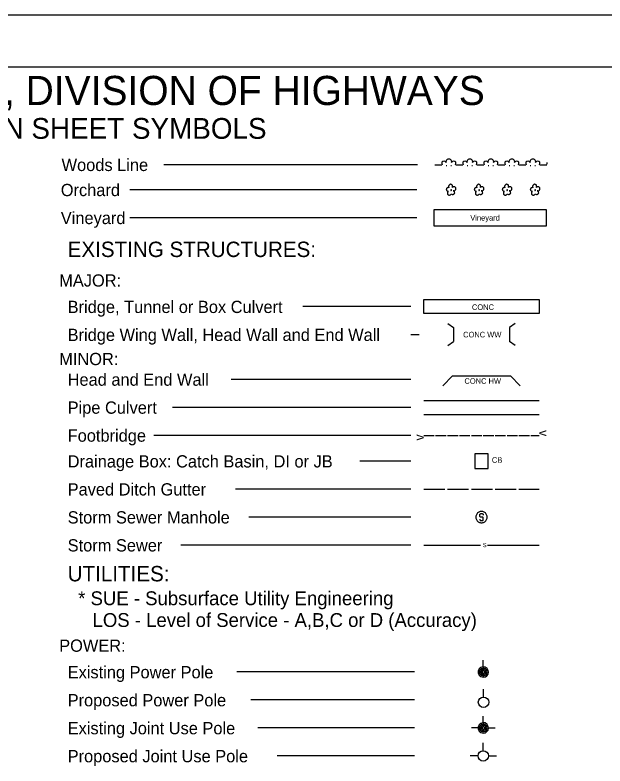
# Model space of a CAD drawing. Extents: x 1552903 to 1553044, y 811448 to 811540.
# Drawn here: x 1552973.4 to 1553008.81, y 811494.96 to 811540.09 of the extents above; entities that cross this region are included whole.
import ezdxf

# ---------------------------------------------------------------- set-up
doc = ezdxf.new("R2010")
doc.units = 0
for name, color, linetype in [('Exist DTM Breakline', 7, 'Continuous'), ('Exist Structure Major Bridge WW', 7, 'Continuous'), ('z - Construction', 7, 'Continuous')]:
    doc.layers.add(name, color=color, linetype=linetype)

msp = doc.modelspace()

# ---------------------------------------------------------------- linework, layer by layer
at = {"layer": 'Exist DTM Breakline'}
for p, q in [((1552997.561, 811531.092), (1552982.332, 811531.092)), ((1552998.603, 811531.092), (1552999.023, 811531.092)), ((1552999.271, 811531.05), (1552999.313, 811531.05)), ((1552999.566, 811531.05), (1552999.608, 811531.05)), ((1552999.864, 811531.092), (1553000.285, 811531.092)), ((1553000.533, 811531.05), (1553000.575, 811531.05)), ((1553000.827, 811531.05), (1553000.869, 811531.05)), ((1553001.125, 811531.092), (1553001.546, 811531.092)), ((1553001.794, 811531.05), (1553001.836, 811531.05)), ((1553002.088, 811531.05), (1553002.13, 811531.05)), ((1553002.386, 811531.092), (1553002.807, 811531.092)), ((1553003.055, 811531.05), (1553003.097, 811531.05)), ((1553003.349, 811531.05), (1553003.391, 811531.05)), ((1553003.648, 811531.092), (1553004.068, 811531.092)), ((1553004.316, 811531.05), (1553004.358, 811531.05)), ((1553004.61, 811531.05), (1553004.652, 811531.05)), ((1553004.909, 811531.092), (1553005.329, 811531.092)), ((1552997.514, 811529.585), (1552980.283, 811529.585)), ((1552997.514, 811527.903), (1552980.283, 811527.903)), ((1552997.151, 811522.564), (1552990.679, 811522.564)), ((1552999.375, 811521.543), (1552999.719, 811521.303)), ((1552999.719, 811521.303), (1552999.719, 811520.462)), ((1553003.427, 811521.543), (1553003.082, 811521.303)), ((1553003.082, 811521.303), (1553003.082, 811520.462)), ((1552997.151, 811520.882), (1552997.654, 811520.882)), ((1552999.375, 811520.221), (1552999.719, 811520.462)), ((1553003.427, 811520.221), (1553003.082, 811520.462)), ((1552997.151, 811518.192), (1552986.363, 811518.192)), ((1552999.072, 811517.808), (1552999.667, 811518.403)), ((1552999.667, 811518.403), (1553003.135, 811518.403)), ((1553003.135, 811518.403), (1553003.73, 811517.808)), ((1552997.933, 811516.931), (1553004.869, 811516.931)), ((1552997.151, 811516.511), (1552982.842, 811516.511)), ((1552997.933, 811516.09), (1553004.869, 811516.09)), ((1552997.151, 811514.829), (1552981.724, 811514.829)), ((1552997.933, 811514.829), (1552998.563, 811514.829)), ((1552998.647, 811514.829), (1552999.278, 811514.829)), ((1552999.362, 811514.829), (1552999.993, 811514.829)), ((1553000.077, 811514.829), (1553000.707, 811514.829)), ((1553000.791, 811514.829), (1553001.422, 811514.829)), ((1553001.506, 811514.829), (1553002.137, 811514.829)), ((1553002.221, 811514.829), (1553002.851, 811514.829)), ((1553002.935, 811514.829), (1553003.566, 811514.829)), ((1553003.65, 811514.829), (1553004.28, 811514.829)), ((1553004.365, 811514.829), (1553004.869, 811514.829)), ((1552997.151, 811513.279), (1552994.099, 811513.279)), ((1552997.151, 811511.598), (1552986.625, 811511.598)), ((1552997.933, 811511.598), (1552999.194, 811511.598)), ((1552999.362, 811511.598), (1553000.623, 811511.598)), ((1553000.791, 811511.598), (1553002.052, 811511.598)), ((1553002.221, 811511.598), (1553003.482, 811511.598)), ((1553003.65, 811511.598), (1553004.869, 811511.598)), ((1552997.151, 811509.916), (1552987.425, 811509.916)), ((1553001.3, 811509.976), (1553001.3, 811510.066)), ((1553001.36, 811510.126), (1553001.45, 811510.126)), ((1553001.45, 811509.919), (1553001.36, 811509.919)), ((1553001.507, 811510.066), (1553001.507, 811510.036)), ((1553001.3, 811509.798), (1553001.3, 811509.768)), ((1553001.36, 811509.711), (1553001.45, 811509.711)), ((1553001.507, 811509.768), (1553001.507, 811509.861)), ((1552997.151, 811508.234), (1552983.345, 811508.234)), ((1552997.933, 811508.234), (1553001.34, 811508.234)), ((1553001.76, 811508.234), (1553004.869, 811508.234)), ((1553001.506, 811500.92), (1553001.506, 811501.324)), ((1552997.385, 811500.61), (1552986.718, 811500.61)), ((1553001.524, 811499.106), (1553001.524, 811499.579)), ((1552997.385, 811498.928), (1552987.549, 811498.928)), ((1553001.506, 811497.557), (1553001.506, 811497.961)), ((1552997.385, 811497.247), (1552987.976, 811497.247)), ((1553001.196, 811497.247), (1553000.792, 811497.247)), ((1553001.816, 811497.247), (1553002.22, 811497.247)), ((1553001.506, 811495.882), (1553001.506, 811496.355)), ((1552997.385, 811495.565), (1552989.126, 811495.565)), ((1553001.191, 811495.566), (1553000.718, 811495.566)), ((1553001.821, 811495.566), (1553002.294, 811495.566))]:
    msp.add_line(p, q, dxfattribs=at)
for points in [[(1552999.653, 811529.732), (1552999.665, 811529.757), (1552999.669, 811529.783), (1552999.665, 811529.808), (1552999.661, 811529.833), (1552999.648, 811529.854), (1552999.636, 811529.875), (1552999.615, 811529.892), (1552999.594, 811529.904), (1552999.564, 811529.913), (1552999.543, 811529.913), (1552999.518, 811529.909), (1552999.493, 811529.9), (1552999.472, 811529.888), (1552999.451, 811529.871), (1552999.438, 811529.846), (1552999.43, 811529.825), (1552999.426, 811529.799), (1552999.426, 811529.774), (1552999.43, 811529.749), (1552999.442, 811529.728), (1552999.459, 811529.703), (1552999.438, 811529.715), (1552999.413, 811529.719), (1552999.388, 811529.719), (1552999.367, 811529.711), (1552999.346, 811529.703), (1552999.325, 811529.686), (1552999.308, 811529.669), (1552999.295, 811529.648), (1552999.291, 811529.627), (1552999.287, 811529.598), (1552999.291, 811529.577), (1552999.3, 811529.556), (1552999.316, 811529.534), (1552999.329, 811529.518), (1552999.35, 811529.505), (1552999.375, 811529.492), (1552999.396, 811529.488), (1552999.421, 811529.488), (1552999.4, 811529.48), (1552999.379, 811529.463), (1552999.367, 811529.446), (1552999.358, 811529.421), (1552999.35, 811529.396), (1552999.35, 811529.375), (1552999.354, 811529.35), (1552999.367, 811529.329), (1552999.379, 811529.307), (1552999.396, 811529.291), (1552999.417, 811529.278), (1552999.438, 811529.27), (1552999.463, 811529.27), (1552999.489, 811529.27), (1552999.51, 811529.274), (1552999.531, 811529.291), (1552999.552, 811529.303), (1552999.573, 811529.341)], [(1552999.573, 811529.341), (1552999.623, 811529.312), (1552999.648, 811529.303), (1552999.674, 811529.299), (1552999.699, 811529.303), (1552999.72, 811529.312), (1552999.741, 811529.324), (1552999.762, 811529.341), (1552999.775, 811529.362), (1552999.783, 811529.383), (1552999.791, 811529.408), (1552999.787, 811529.434), (1552999.783, 811529.459), (1552999.766, 811529.484), (1552999.754, 811529.501), (1552999.733, 811529.513), (1552999.707, 811529.526), (1552999.733, 811529.522), (1552999.762, 811529.522), (1552999.783, 811529.53), (1552999.808, 811529.543), (1552999.829, 811529.556), (1552999.846, 811529.577), (1552999.859, 811529.602), (1552999.863, 811529.627), (1552999.867, 811529.652), (1552999.863, 811529.677), (1552999.854, 811529.703), (1552999.838, 811529.724), (1552999.817, 811529.745), (1552999.796, 811529.757), (1552999.77, 811529.766), (1552999.745, 811529.77), (1552999.72, 811529.77), (1552999.695, 811529.762), (1552999.674, 811529.749), (1552999.653, 811529.732)], [(1553001.334, 811529.732), (1553001.347, 811529.757), (1553001.351, 811529.783), (1553001.347, 811529.808), (1553001.343, 811529.833), (1553001.33, 811529.854), (1553001.317, 811529.875), (1553001.296, 811529.892), (1553001.275, 811529.904), (1553001.246, 811529.913), (1553001.225, 811529.913), (1553001.2, 811529.909), (1553001.174, 811529.9), (1553001.153, 811529.888), (1553001.132, 811529.871), (1553001.12, 811529.846), (1553001.111, 811529.825), (1553001.107, 811529.799), (1553001.107, 811529.774), (1553001.111, 811529.749), (1553001.124, 811529.728), (1553001.141, 811529.703), (1553001.12, 811529.715), (1553001.095, 811529.719), (1553001.069, 811529.719), (1553001.048, 811529.711), (1553001.027, 811529.703), (1553001.006, 811529.686), (1553000.99, 811529.669), (1553000.977, 811529.648), (1553000.973, 811529.627), (1553000.968, 811529.598), (1553000.973, 811529.577), (1553000.981, 811529.556), (1553000.998, 811529.534), (1553001.011, 811529.518), (1553001.032, 811529.505), (1553001.057, 811529.492), (1553001.078, 811529.488), (1553001.103, 811529.488), (1553001.082, 811529.48), (1553001.061, 811529.463), (1553001.048, 811529.446), (1553001.04, 811529.421), (1553001.032, 811529.396), (1553001.032, 811529.375), (1553001.036, 811529.35), (1553001.048, 811529.329), (1553001.061, 811529.307), (1553001.078, 811529.291), (1553001.099, 811529.278), (1553001.12, 811529.27), (1553001.145, 811529.27), (1553001.17, 811529.27), (1553001.191, 811529.274), (1553001.212, 811529.291), (1553001.233, 811529.303), (1553001.254, 811529.341)], [(1553001.254, 811529.341), (1553001.305, 811529.312), (1553001.33, 811529.303), (1553001.355, 811529.299), (1553001.38, 811529.303), (1553001.401, 811529.312), (1553001.423, 811529.324), (1553001.444, 811529.341), (1553001.456, 811529.362), (1553001.465, 811529.383), (1553001.473, 811529.408), (1553001.469, 811529.434), (1553001.465, 811529.459), (1553001.448, 811529.484), (1553001.435, 811529.501), (1553001.414, 811529.513), (1553001.389, 811529.526), (1553001.414, 811529.522), (1553001.444, 811529.522), (1553001.465, 811529.53), (1553001.49, 811529.543), (1553001.511, 811529.556), (1553001.528, 811529.577), (1553001.54, 811529.602), (1553001.544, 811529.627), (1553001.549, 811529.652), (1553001.544, 811529.677), (1553001.536, 811529.703), (1553001.519, 811529.724), (1553001.498, 811529.745), (1553001.477, 811529.757), (1553001.452, 811529.766), (1553001.427, 811529.77), (1553001.401, 811529.77), (1553001.376, 811529.762), (1553001.355, 811529.749), (1553001.334, 811529.732)], [(1553003.016, 811529.732), (1553003.028, 811529.757), (1553003.033, 811529.783), (1553003.028, 811529.808), (1553003.024, 811529.833), (1553003.012, 811529.854), (1553002.999, 811529.875), (1553002.978, 811529.892), (1553002.957, 811529.904), (1553002.928, 811529.913), (1553002.906, 811529.913), (1553002.881, 811529.909), (1553002.856, 811529.9), (1553002.835, 811529.888), (1553002.814, 811529.871), (1553002.801, 811529.846), (1553002.793, 811529.825), (1553002.789, 811529.799), (1553002.789, 811529.774), (1553002.793, 811529.749), (1553002.806, 811529.728), (1553002.822, 811529.703), (1553002.801, 811529.715), (1553002.776, 811529.719), (1553002.751, 811529.719), (1553002.73, 811529.711), (1553002.709, 811529.703), (1553002.688, 811529.686), (1553002.671, 811529.669), (1553002.658, 811529.648), (1553002.654, 811529.627), (1553002.65, 811529.598), (1553002.654, 811529.577), (1553002.663, 811529.556), (1553002.679, 811529.534), (1553002.692, 811529.518), (1553002.713, 811529.505), (1553002.738, 811529.492), (1553002.759, 811529.488), (1553002.785, 811529.488), (1553002.764, 811529.48), (1553002.743, 811529.463), (1553002.73, 811529.446), (1553002.722, 811529.421), (1553002.713, 811529.396), (1553002.713, 811529.375), (1553002.717, 811529.35), (1553002.73, 811529.329), (1553002.743, 811529.307), (1553002.759, 811529.291), (1553002.78, 811529.278), (1553002.801, 811529.27), (1553002.827, 811529.27), (1553002.852, 811529.27), (1553002.873, 811529.274), (1553002.894, 811529.291), (1553002.915, 811529.303), (1553002.936, 811529.341)], [(1553002.936, 811529.341), (1553002.986, 811529.312), (1553003.012, 811529.303), (1553003.037, 811529.299), (1553003.062, 811529.303), (1553003.083, 811529.312), (1553003.104, 811529.324), (1553003.125, 811529.341), (1553003.138, 811529.362), (1553003.146, 811529.383), (1553003.155, 811529.408), (1553003.15, 811529.434), (1553003.146, 811529.459), (1553003.129, 811529.484), (1553003.117, 811529.501), (1553003.096, 811529.513), (1553003.07, 811529.526), (1553003.096, 811529.522), (1553003.125, 811529.522), (1553003.146, 811529.53), (1553003.171, 811529.543), (1553003.192, 811529.556), (1553003.209, 811529.577), (1553003.222, 811529.602), (1553003.226, 811529.627), (1553003.23, 811529.652), (1553003.226, 811529.677), (1553003.218, 811529.703), (1553003.201, 811529.724), (1553003.18, 811529.745), (1553003.159, 811529.757), (1553003.134, 811529.766), (1553003.108, 811529.77), (1553003.083, 811529.77), (1553003.058, 811529.762), (1553003.037, 811529.749), (1553003.016, 811529.732)], [(1553004.697, 811529.732), (1553004.71, 811529.757), (1553004.714, 811529.783), (1553004.71, 811529.808), (1553004.706, 811529.833), (1553004.693, 811529.854), (1553004.681, 811529.875), (1553004.66, 811529.892), (1553004.639, 811529.904), (1553004.609, 811529.913), (1553004.588, 811529.913), (1553004.563, 811529.909), (1553004.538, 811529.9), (1553004.517, 811529.888), (1553004.496, 811529.871), (1553004.483, 811529.846), (1553004.475, 811529.825), (1553004.47, 811529.799), (1553004.47, 811529.774), (1553004.475, 811529.749), (1553004.487, 811529.728), (1553004.504, 811529.703), (1553004.483, 811529.715), (1553004.458, 811529.719), (1553004.433, 811529.719), (1553004.411, 811529.711), (1553004.39, 811529.703), (1553004.369, 811529.686), (1553004.353, 811529.669), (1553004.34, 811529.648), (1553004.336, 811529.627), (1553004.332, 811529.598), (1553004.336, 811529.577), (1553004.344, 811529.556), (1553004.361, 811529.534), (1553004.374, 811529.518), (1553004.395, 811529.505), (1553004.42, 811529.492), (1553004.441, 811529.488), (1553004.466, 811529.488), (1553004.445, 811529.48), (1553004.424, 811529.463), (1553004.411, 811529.446), (1553004.403, 811529.421), (1553004.395, 811529.396), (1553004.395, 811529.375), (1553004.399, 811529.35), (1553004.411, 811529.329), (1553004.424, 811529.307), (1553004.441, 811529.291), (1553004.462, 811529.278), (1553004.483, 811529.27), (1553004.508, 811529.27), (1553004.533, 811529.27), (1553004.554, 811529.274), (1553004.575, 811529.291), (1553004.596, 811529.303), (1553004.617, 811529.341)], [(1553004.617, 811529.341), (1553004.668, 811529.312), (1553004.693, 811529.303), (1553004.718, 811529.299), (1553004.744, 811529.303), (1553004.765, 811529.312), (1553004.786, 811529.324), (1553004.807, 811529.341), (1553004.819, 811529.362), (1553004.828, 811529.383), (1553004.836, 811529.408), (1553004.832, 811529.434), (1553004.828, 811529.459), (1553004.811, 811529.484), (1553004.798, 811529.501), (1553004.777, 811529.513), (1553004.752, 811529.526), (1553004.777, 811529.522), (1553004.807, 811529.522), (1553004.828, 811529.53), (1553004.853, 811529.543), (1553004.874, 811529.556), (1553004.891, 811529.577), (1553004.903, 811529.602), (1553004.908, 811529.627), (1553004.912, 811529.652), (1553004.908, 811529.677), (1553004.899, 811529.703), (1553004.882, 811529.724), (1553004.861, 811529.745), (1553004.84, 811529.757), (1553004.815, 811529.766), (1553004.79, 811529.77), (1553004.765, 811529.77), (1553004.739, 811529.762), (1553004.718, 811529.749), (1553004.697, 811529.732)], [(1552999.581, 811529.585), (1552999.569, 811529.585), (1552999.56, 811529.581), (1552999.552, 811529.577), (1552999.552, 811529.564), (1552999.552, 811529.556), (1552999.56, 811529.547), (1552999.573, 811529.547), (1552999.581, 811529.547), (1552999.59, 811529.556), (1552999.594, 811529.568), (1552999.59, 811529.577), (1552999.581, 811529.585)], [(1553001.263, 811529.585), (1553001.25, 811529.585), (1553001.242, 811529.581), (1553001.233, 811529.577), (1553001.233, 811529.564), (1553001.233, 811529.556), (1553001.242, 811529.547), (1553001.254, 811529.547), (1553001.263, 811529.547), (1553001.271, 811529.556), (1553001.275, 811529.568), (1553001.271, 811529.577), (1553001.263, 811529.585)], [(1553002.944, 811529.585), (1553002.932, 811529.585), (1553002.923, 811529.581), (1553002.915, 811529.577), (1553002.915, 811529.564), (1553002.915, 811529.556), (1553002.923, 811529.547), (1553002.936, 811529.547), (1553002.944, 811529.547), (1553002.953, 811529.556), (1553002.957, 811529.568), (1553002.953, 811529.577), (1553002.944, 811529.585)], [(1553004.626, 811529.585), (1553004.613, 811529.585), (1553004.605, 811529.581), (1553004.596, 811529.577), (1553004.596, 811529.564), (1553004.596, 811529.556), (1553004.605, 811529.547), (1553004.617, 811529.547), (1553004.626, 811529.547), (1553004.634, 811529.556), (1553004.639, 811529.568), (1553004.634, 811529.577), (1553004.626, 811529.585)], [(1552998.555, 811528.408), (1553005.282, 811528.408), (1553005.282, 811527.399), (1552998.555, 811527.399), (1552998.555, 811528.408)], [(1552997.933, 811522.984), (1553004.869, 811522.984), (1553004.869, 811522.144), (1552997.933, 811522.144), (1552997.933, 811522.984)], [(1553001.401, 811510.257), (1553001.357, 811510.255), (1553001.316, 811510.246), (1553001.275, 811510.233), (1553001.237, 811510.214), (1553001.201, 811510.192), (1553001.169, 811510.164), (1553001.139, 811510.132), (1553001.114, 811510.099), (1553001.092, 811510.061), (1553001.079, 811510.02), (1553001.068, 811509.979), (1553001.062, 811509.938), (1553001.062, 811509.894), (1553001.068, 811509.853), (1553001.079, 811509.81), (1553001.092, 811509.771), (1553001.114, 811509.733), (1553001.139, 811509.7), (1553001.169, 811509.667), (1553001.201, 811509.64), (1553001.237, 811509.618), (1553001.275, 811509.599), (1553001.316, 811509.585), (1553001.36, 811509.577), (1553001.401, 811509.575), (1553001.445, 811509.577), (1553001.485, 811509.585), (1553001.526, 811509.599), (1553001.565, 811509.618), (1553001.6, 811509.64), (1553001.633, 811509.667), (1553001.663, 811509.7), (1553001.688, 811509.733), (1553001.709, 811509.771), (1553001.723, 811509.812), (1553001.734, 811509.853), (1553001.739, 811509.894), (1553001.739, 811509.938), (1553001.734, 811509.979), (1553001.723, 811510.022), (1553001.709, 811510.061), (1553001.688, 811510.099), (1553001.663, 811510.132), (1553001.633, 811510.164), (1553001.6, 811510.192), (1553001.565, 811510.214), (1553001.526, 811510.233), (1553001.485, 811510.246), (1553001.442, 811510.255), (1553001.401, 811510.257)], [(1553001.3, 811510.066), (1553001.305, 811510.085), (1553001.313, 811510.102), (1553001.324, 811510.113), (1553001.341, 811510.121), (1553001.36, 811510.126)], [(1553001.36, 811509.919), (1553001.341, 811509.921), (1553001.324, 811509.93), (1553001.313, 811509.943), (1553001.305, 811509.96), (1553001.3, 811509.976)], [(1553001.45, 811510.126), (1553001.466, 811510.121), (1553001.483, 811510.113), (1553001.496, 811510.102), (1553001.505, 811510.085), (1553001.507, 811510.066)], [(1553001.507, 811509.859), (1553001.505, 811509.878), (1553001.496, 811509.894), (1553001.483, 811509.908), (1553001.466, 811509.916), (1553001.45, 811509.919)], [(1553001.3, 811509.771), (1553001.305, 811509.752), (1553001.313, 811509.736), (1553001.324, 811509.722), (1553001.341, 811509.714), (1553001.36, 811509.711)], [(1553001.45, 811509.711), (1553001.466, 811509.714), (1553001.483, 811509.722), (1553001.496, 811509.736), (1553001.505, 811509.752), (1553001.507, 811509.771)], [(1553001.736, 811500.61), (1553001.729, 811500.666), (1553001.711, 811500.716), (1553001.68, 811500.759), (1553001.642, 811500.796), (1553001.599, 811500.821), (1553001.543, 811500.833), (1553001.493, 811500.84), (1553001.438, 811500.827), (1553001.388, 811500.809), (1553001.351, 811500.778), (1553001.314, 811500.734), (1553001.289, 811500.691), (1553001.276, 811500.635), (1553001.276, 811500.585), (1553001.289, 811500.529), (1553001.314, 811500.486), (1553001.351, 811500.442), (1553001.388, 811500.411), (1553001.438, 811500.393), (1553001.493, 811500.38), (1553001.543, 811500.387), (1553001.599, 811500.399), (1553001.642, 811500.424), (1553001.68, 811500.461), (1553001.711, 811500.505), (1553001.729, 811500.554), (1553001.736, 811500.61)], [(1553001.661, 811500.61), (1553001.655, 811500.654), (1553001.636, 811500.697), (1553001.605, 811500.728), (1553001.568, 811500.753), (1553001.531, 811500.765), (1553001.481, 811500.765), (1553001.444, 811500.753), (1553001.407, 811500.728), (1553001.376, 811500.697), (1553001.357, 811500.654), (1553001.351, 811500.61), (1553001.357, 811500.567), (1553001.376, 811500.523), (1553001.407, 811500.492), (1553001.444, 811500.467), (1553001.481, 811500.455), (1553001.531, 811500.455), (1553001.568, 811500.467), (1553001.605, 811500.492), (1553001.636, 811500.523), (1553001.655, 811500.567), (1553001.661, 811500.61)], [(1553001.58, 811500.61), (1553001.574, 811500.641), (1553001.556, 811500.666), (1553001.531, 811500.678), (1553001.5, 811500.685), (1553001.469, 811500.672), (1553001.444, 811500.654), (1553001.431, 811500.623), (1553001.431, 811500.598), (1553001.444, 811500.567), (1553001.469, 811500.548), (1553001.5, 811500.536), (1553001.531, 811500.542), (1553001.556, 811500.554), (1553001.574, 811500.579), (1553001.58, 811500.61)], [(1553001.736, 811497.247), (1553001.729, 811497.303), (1553001.711, 811497.352), (1553001.68, 811497.396), (1553001.642, 811497.433), (1553001.599, 811497.458), (1553001.543, 811497.47), (1553001.493, 811497.477), (1553001.438, 811497.464), (1553001.388, 811497.446), (1553001.351, 811497.415), (1553001.314, 811497.371), (1553001.289, 811497.328), (1553001.276, 811497.272), (1553001.276, 811497.222), (1553001.289, 811497.166), (1553001.314, 811497.123), (1553001.351, 811497.079), (1553001.388, 811497.048), (1553001.438, 811497.03), (1553001.493, 811497.017), (1553001.543, 811497.024), (1553001.599, 811497.036), (1553001.642, 811497.061), (1553001.68, 811497.098), (1553001.711, 811497.141), (1553001.729, 811497.191), (1553001.736, 811497.247)], [(1553001.661, 811497.247), (1553001.655, 811497.29), (1553001.636, 811497.334), (1553001.605, 811497.365), (1553001.568, 811497.39), (1553001.531, 811497.402), (1553001.481, 811497.402), (1553001.444, 811497.39), (1553001.407, 811497.365), (1553001.376, 811497.334), (1553001.357, 811497.29), (1553001.351, 811497.247), (1553001.357, 811497.203), (1553001.376, 811497.16), (1553001.407, 811497.129), (1553001.444, 811497.104), (1553001.481, 811497.092), (1553001.531, 811497.092), (1553001.568, 811497.104), (1553001.605, 811497.129), (1553001.636, 811497.16), (1553001.655, 811497.203), (1553001.661, 811497.247)], [(1553001.58, 811497.247), (1553001.574, 811497.278), (1553001.556, 811497.303), (1553001.531, 811497.315), (1553001.5, 811497.321), (1553001.469, 811497.309), (1553001.444, 811497.29), (1553001.431, 811497.259), (1553001.431, 811497.234), (1553001.444, 811497.203), (1553001.469, 811497.185), (1553001.5, 811497.172), (1553001.531, 811497.179), (1553001.556, 811497.191), (1553001.574, 811497.216), (1553001.58, 811497.247)]]:
    msp.add_lwpolyline(points, dxfattribs=at)
for points in [[(1553000.996, 811512.832), (1553001.804, 811512.832), (1553001.804, 811513.727), (1553000.996, 811513.727)], [(1553001.506, 811500.3), (1553001.636, 811500.324), (1553001.723, 811500.387), (1553001.791, 811500.474), (1553001.816, 811500.591), (1553001.804, 811500.703), (1553001.742, 811500.815), (1553001.618, 811500.908), (1553001.475, 811500.92), (1553001.351, 811500.883), (1553001.252, 811500.796), (1553001.202, 811500.678), (1553001.202, 811500.542), (1553001.252, 811500.424), (1553001.363, 811500.331)], [(1553001.506, 811496.937), (1553001.636, 811496.961), (1553001.723, 811497.024), (1553001.791, 811497.11), (1553001.816, 811497.228), (1553001.804, 811497.34), (1553001.742, 811497.452), (1553001.618, 811497.545), (1553001.475, 811497.557), (1553001.351, 811497.52), (1553001.252, 811497.433), (1553001.202, 811497.315), (1553001.202, 811497.179), (1553001.252, 811497.061), (1553001.363, 811496.968)]]:
    msp.add_lwpolyline(points, close=True, dxfattribs=at)
for centre in [(1553001.524, 811498.791), (1553001.506, 811495.565)]:
    msp.add_circle(centre, 0.315, dxfattribs=at)
for centre, radius, start, end in [((1552999.145, 811531.178), 0.133, 18.435, 219.2315), ((1552999.44, 811531.262), 0.173, 345.9638, 194.0362), ((1552999.734, 811531.178), 0.133, 320.7685, 161.5651), ((1553000.406, 811531.178), 0.133, 18.435, 219.2315), ((1553000.701, 811531.262), 0.173, 345.9638, 194.0362), ((1553000.995, 811531.178), 0.133, 320.7685, 161.5651), ((1553001.667, 811531.178), 0.133, 18.435, 219.2315), ((1553001.962, 811531.262), 0.173, 345.9638, 194.0362), ((1553002.256, 811531.178), 0.133, 320.7685, 161.5651), ((1553002.929, 811531.178), 0.133, 18.435, 219.2315), ((1553003.223, 811531.262), 0.173, 345.9638, 194.0362), ((1553003.517, 811531.178), 0.133, 320.7685, 161.5651), ((1553004.19, 811531.178), 0.133, 18.435, 219.2315), ((1553004.484, 811531.262), 0.173, 345.9638, 194.0362), ((1553004.778, 811531.178), 0.133, 320.7685, 161.5651), ((1553005.451, 811531.178), 0.133, 156.251, 203.749)]:
    msp.add_arc(centre, radius, start, end, dxfattribs=at)
at = {"layer": 'Exist Structure Major Bridge WW'}
msp.add_line((1553041.105, 811536.962), (1552905.688, 811536.962), dxfattribs=at)
at = {"layer": 'z - Construction'}
msp.add_line((1553044.23, 811540.087), (1552902.563, 811540.087), dxfattribs=at)

# ---------------------------------------------------------------- texts
at = {"layer": 'Exist DTM Breakline'}
for s, height, p in [('STATE OF NORTH CAROLINA, DIVISION OF HIGHWAYS', 1.75, (1552939.708, 811534.68)), ('CONVENTIONAL  PLAN SHEET SYMBOLS', 1.25, (1552955.429, 811532.649)), ('Woods Line', 0.7357, (1552976.192, 811530.712)), ('Orchard', 0.7357, (1552976.144, 811529.204)), ('Vineyard', 0.7357, (1552976.144, 811527.523)), ('EXISTING STRUCTURES:', 0.92486, (1552976.555, 811525.544)), ('MAJOR:', 0.7357, (1552976.048, 811523.769)), ('Bridge, Tunnel or Box Culvert', 0.73569, (1552976.555, 811522.181)), ('CONC', 0.3363, (1553000.828, 811522.365)), ('Bridge Wing Wall, Head Wall and End Wall', 0.73569, (1552976.555, 811520.5)), ('MINOR:', 0.7357, (1552976.048, 811519.05)), ('Head and End Wall', 0.73569, (1552976.555, 811517.81)), ('CONC HW', 0.3363, (1553000.375, 811517.926)), ('Pipe Culvert', 0.73569, (1552976.555, 811516.129)), ('Footbridge', 0.7357, (1552976.556, 811514.448)), ('Drainage Box: Catch Basin, DI or JB', 0.73569, (1552976.556, 811512.898)), ('CB', 0.3363, (1553002.026, 811513.18)), ('Paved Ditch Gutter', 0.73569, (1552976.556, 811511.215)), ('Storm Sewer Manhole', 0.73569, (1552976.556, 811509.533)), ('Storm Sewer', 0.73569, (1552976.556, 811507.852)), ('S', 0.252, (1553001.474, 811508.108)), ('UTILITIES:', 0.9249, (1552976.555, 811506.055)), ('* SUE - Subsurface Utility Engineering', 0.83238, (1552977.188, 811504.624)), ('LOS - Level of Service - A,B,C or D (Accuracy) ', 0.83238, (1552978.051, 811503.315)), ('POWER:', 0.7357, (1552976.048, 811501.826)), ('Existing Power Pole', 0.73569, (1552976.556, 811500.229)), ('Proposed Power Pole', 0.73569, (1552976.556, 811498.547)), ('Existing Joint Use Pole', 0.73569, (1552976.556, 811496.866)), ('Proposed Joint Use Pole', 0.73569, (1552976.557, 811495.184))]:
    msp.add_text(s, height=height, dxfattribs=at).set_placement(p)
for s, height, rotation, p in [('Vineyard', 0.3363, 0, (1553000.727, 811527.735)), ('CONC WW', 0.3363, 0, (1553000.297, 811520.714)), ('v', 0.555, 89.7591, (1552997.932, 811514.515)), ('v', 0.555, 270.2409, (1553004.868, 811515.143))]:
    msp.add_text(s, height=height, rotation=rotation, dxfattribs=at).set_placement(p)

doc.saveas('drawing.dxf')
